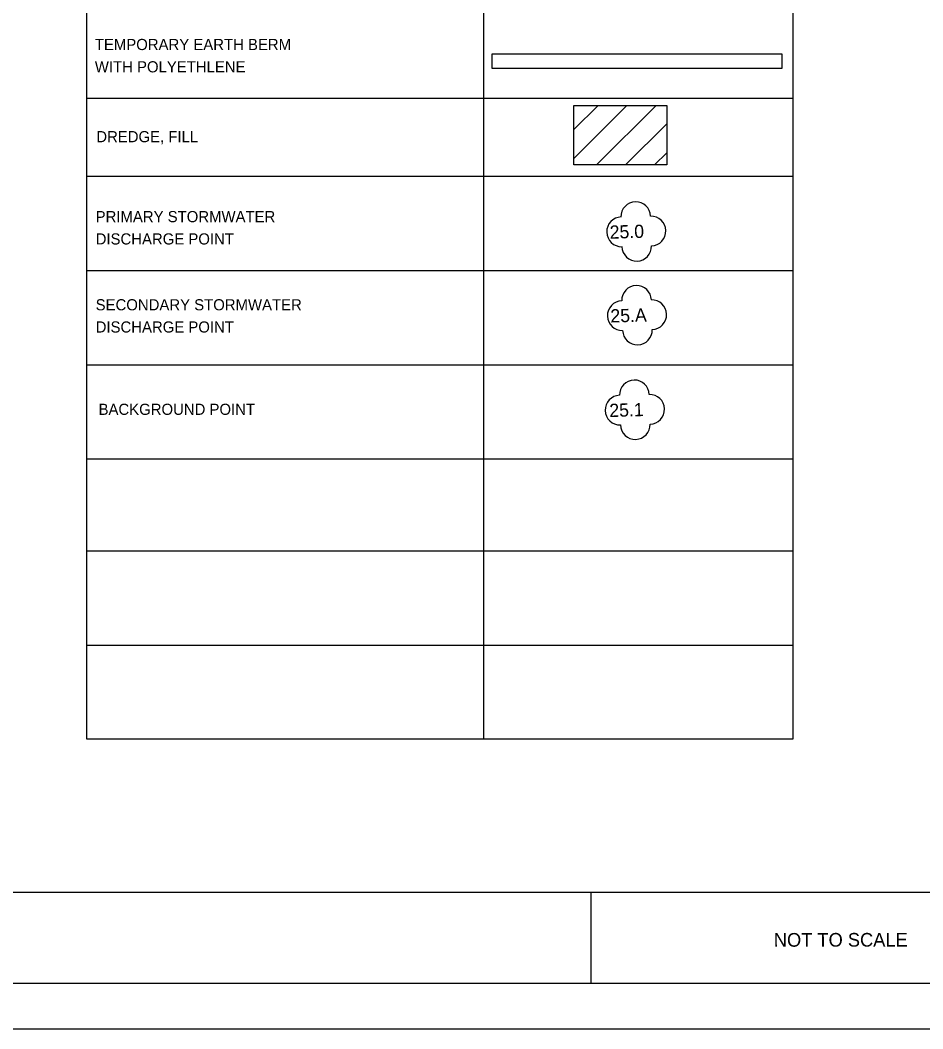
# Model space of a CAD drawing. Extents: x 1539684 to 1543084, y 305681 to 307881.
# Drawn here: x 1541341 to 1542333, y 305681 to 306788 of the extents above; entities that cross this region are included whole.
import ezdxf

# ---------------------------------------------------------------- set-up
doc = ezdxf.new("R2010")
doc.units = 0
for name, color, linetype in [('ANNO-SYMB', 7, 'Continuous'), ('Default', 7, 'Continuous'), ('Level 1', 7, 'Continuous'), ('Level 62', 7, 'Continuous'), ('SHT-BDR', 7, 'Continuous'), ('SHT-BNDRY', 7, 'Continuous')]:
    doc.layers.add(name, color=color, linetype=linetype)

msp = doc.modelspace()

# ---------------------------------------------------------------- linework, layer by layer
at = {"layer": 'Default'}
for p, q in [((1541850.2, 305999.7), (1541850.2, 307287.9)), ((1541414.2, 306702.6), (1542189.9, 306702.6)), ((1541949.2, 306668.3), (1541975.8, 306694.8)), ((1541949.2, 306636.4), (1542007.6, 306694.8)), ((1541949.2, 306668.3), (1541975.8, 306694.8)), ((1541949.2, 306636.4), (1542007.6, 306694.8)), ((1541974, 306629.4), (1542039.5, 306694.8)), ((1541974, 306629.4), (1542039.5, 306694.8)), ((1542005.9, 306629.4), (1542051.2, 306674.7)), ((1542005.9, 306629.4), (1542051.2, 306674.7)), ((1542037.7, 306629.4), (1542051.2, 306642.9)), ((1542037.7, 306629.4), (1542051.2, 306642.9)), ((1541414.2, 306617), (1542189.9, 306617)), ((1542002, 306539.8), (1542002, 306539.7)), ((1541414.2, 306513.5), (1542189.9, 306513.5)), ((1541414.2, 306513.5), (1542189.9, 306513.5)), ((1542002.8, 306447.8), (1542002.8, 306447.7)), ((1541414.2, 306410.1), (1542189.9, 306410.1)), ((1541414.2, 306410.1), (1542189.9, 306410.1)), ((1542000.4, 306343.9), (1542000.5, 306343.9)), ((1541414.2, 306306.7), (1542189.9, 306306.7)), ((1541414.2, 306205.6), (1542189.9, 306205.6)), ((1541414.2, 306102.2), (1542189.9, 306102.2))]:
    msp.add_line(p, q, dxfattribs=at)
for points in [[(1541414.2, 307287.9), (1542189.9, 307287.9), (1542189.9, 305998.8), (1541414.2, 305998.8)], [(1541859.7, 306751.6), (1542177.6, 306751.6), (1542177.6, 306735.3), (1541859.7, 306735.3)], [(1541949.2, 306694.8), (1542051.2, 306694.8), (1542051.2, 306629.4), (1541949.2, 306629.4)], [(1541949.2, 306694.8), (1542051.2, 306694.8), (1542051.2, 306629.4), (1541949.2, 306629.4)]]:
    msp.add_lwpolyline(points, close=True, dxfattribs=at)
for centre, start, end in [((1542017.3, 306572.7), 1.6505, 181.5313), ((1542001.6, 306556), 91.6505, 271.5313), ((1542034, 306556.9), 271.766, 91.6468), ((1542018.3, 306540.2), 181.766, 1.6468), ((1542018.1, 306480.8), 1.6505, 181.5313), ((1542002.4, 306464), 91.6505, 271.5313), ((1542034.8, 306465), 271.766, 91.6468), ((1542019.1, 306448.2), 181.766, 1.6468), ((1542015.8, 306376.9), 1.6505, 181.5313), ((1542000, 306360.2), 91.6505, 271.5313), ((1542032.5, 306361.1), 271.766, 91.6468), ((1542016.7, 306344.4), 181.766, 1.6468)]:
    msp.add_arc(centre, 16.3, start, end, dxfattribs=at)
at = {"layer": 'Level 1'}
msp.add_lwpolyline([(1539808.6, 305730.8), (1543033.6, 305730.8), (1543033.6, 307830.8), (1539808.6, 307830.8)], close=True, dxfattribs=at)
at = {"layer": 'Level 62'}
msp.add_lwpolyline([(1539683.6, 305680.8), (1543083.6, 305680.8), (1543083.6, 307880.8), (1539683.6, 307880.8)], close=True, dxfattribs=at)
at = {"layer": 'SHT-BDR'}
msp.add_lwpolyline([(1539808.6, 305830.9), (1543033.6, 305830.9)], dxfattribs=at)
at = {"layer": 'SHT-BNDRY'}
msp.add_line((1541968.3, 305730.8), (1541968.3, 305830.9), dxfattribs=at)

# ---------------------------------------------------------------- texts
at = {"layer": 'ANNO-SYMB'}
msp.add_text('NOT TO SCALE', height=14.994, rotation=0.0572, dxfattribs=at).set_placement((1542168.9, 305771))
at = {"layer": 'Default'}
for s, p in [('TEMPORARY EARTH BERM', (1541423.1, 306755.6)), ('WITH POLYETHLENE', (1541423.1, 306731.1)), ('DREDGE, FILL', (1541424.7, 306654.4)), ('PRIMARY STORMWATER ', (1541424, 306566.6)), ('DISCHARGE POINT', (1541424, 306542.1)), ('SECONDARY STORMWATER ', (1541424, 306469.8)), ('DISCHARGE POINT', (1541424, 306445.4)), ('BACKGROUND POINT', (1541427.2, 306355))]:
    msp.add_text(s, height=12.24, dxfattribs=at).set_placement(p)
for s, p in [('25.0', (1541988.8, 306548.4)), ('25.A', (1541989.6, 306456.4)), ('25.1', (1541988.4, 306352.6))]:
    msp.add_text(s, height=14.5, rotation=1.6486, dxfattribs=at).set_placement(p)

doc.saveas('drawing.dxf')
